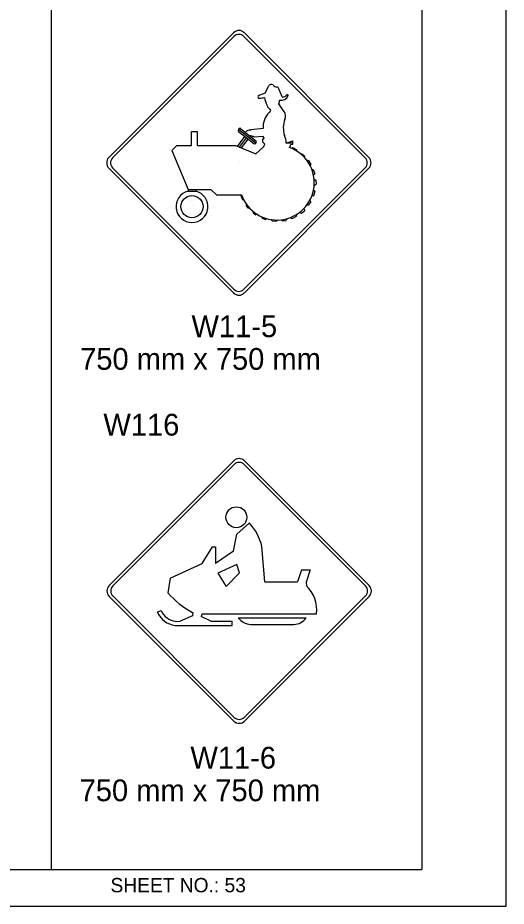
# Model space of a CAD drawing. Extents: x -12 to 6962, y -3756 to 679.
# Drawn here: x 2275 to 2342.4, y -235.4 to -112.9 of the extents above; entities that cross this region are included whole.
import ezdxf

# ---------------------------------------------------------------- set-up
doc = ezdxf.new("R2010")
doc.units = 0
for name, color, linetype in [('Level 1', 7, 'Continuous'), ('Level 2', 7, 'Continuous'), ('Level 3', 7, 'Continuous'), ('Level 62', 7, 'Continuous')]:
    doc.layers.add(name, color=color, linetype=linetype)

msp = doc.modelspace()

# ---------------------------------------------------------------- linework, layer by layer
at = {"layer": 'Level 1'}
for p, q in [((2279.62, -30.35), (2279.62, -230.35)), ((2330.8, -30.35), (2330.8, -230.35)), ((2287.6, -132.14), (2304.78, -114.96)), ((2306.28, -114.96), (2323.46, -132.14)), ((2288.09, -132.21), (2304.84, -115.45)), ((2306.21, -115.45), (2322.97, -132.21)), ((2309.16, -123.29), (2309.62, -122.34)), ((2311.49, -123.81), (2311.05, -122.67)), ((2311.8, -125.84), (2311.06, -124.74)), ((2299.01, -130.5), (2299.01, -128.58)), ((2299.01, -128.58), (2299.8, -128.58)), ((2299.8, -130.5), (2299.8, -128.58)), ((2305.46, -128.56), (2307.58, -130.24)), ((2305.47, -128.25), (2307.87, -130.15)), ((2305.77, -128.17), (2307.89, -129.85)), ((2308.86, -128.17), (2307.18, -128.32)), ((2307.18, -128.32), (2307.18, -128.39)), ((2305.32, -130.62), (2306.36, -129.28)), ((2305.6, -130.72), (2306.58, -129.46)), ((2305.87, -130.84), (2306.81, -129.63)), ((2307.64, -129.36), (2307.48, -129.2)), ((2308.9, -129.24), (2307.64, -129.36)), ((2308.83, -129.61), (2309.04, -129.48)), ((2308.83, -130.06), (2308.83, -129.61)), ((2309.04, -129.48), (2308.9, -129.24)), ((2312.05, -130.17), (2312.95, -129.84)), ((2312.95, -129.84), (2312.95, -130.34)), ((2296.96, -130.5), (2296.28, -131.19)), ((2296.96, -130.5), (2299.01, -130.5)), ((2299.8, -130.5), (2305.04, -130.5)), ((2305.04, -130.5), (2307.85, -131.64)), ((2307.85, -131.64), (2308.96, -130.66)), ((2309.13, -130.32), (2308.83, -130.06)), ((2308.96, -130.66), (2309.13, -130.32)), ((2312.2, -130.12), (2312.94, -130.12)), ((2312.95, -130.34), (2312.65, -130.42)), ((2312.77, -130.89), (2312.95, -130.79)), ((2312.95, -130.79), (2313.52, -131.08)), ((2313.54, -131.28), (2313.52, -131.08)), ((2296.28, -131.19), (2298.51, -136.55)), ((2314.01, -131.63), (2314.22, -131.63)), ((2314.22, -131.63), (2314.62, -131.98)), ((2314.58, -132.16), (2314.62, -131.98)), ((2305.55, -132.77), (2305.55, -132.77)), ((2314.85, -132.48), (2315.13, -132.57)), ((2315.13, -132.57), (2315.47, -133.13)), ((2315.4, -133.36), (2315.47, -133.13)), ((2304.78, -150.82), (2287.6, -133.64)), ((2304.85, -150.33), (2288.09, -133.58)), ((2322.97, -133.58), (2306.22, -150.33)), ((2323.46, -133.64), (2306.28, -150.82)), ((2315.57, -133.74), (2315.77, -133.8)), ((2315.77, -133.8), (2316, -134.41)), ((2315.83, -134.6), (2316, -134.41)), ((2315.91, -135.13), (2316.14, -135.29)), ((2315.92, -136.03), (2316.18, -135.83)), ((2316.14, -135.29), (2316.18, -135.83)), ((2298.51, -136.55), (2301.66, -136.55)), ((2298.51, -136.55), (2298.51, -136.8)), ((2298.51, -136.8), (2299.59, -136.8)), ((2299.59, -136.55), (2299.59, -136.8)), ((2301.66, -136.55), (2302.43, -137.32)), ((2315.83, -136.66), (2316.06, -136.78)), ((2315.89, -137.38), (2316.06, -136.78)), ((2302.43, -137.32), (2305.91, -137.32)), ((2305.91, -137.32), (2305.78, -137.49)), ((2305.78, -137.49), (2306.06, -138.01)), ((2306.25, -138.07), (2306.06, -138.01)), ((2315.2, -138.7), (2315.48, -138.3)), ((2315.33, -138.05), (2315.48, -138.3)), ((2315.61, -137.42), (2315.89, -137.38)), ((2306.54, -138.56), (2306.51, -138.8)), ((2306.51, -138.8), (2306.83, -139.15)), ((2307.06, -139.18), (2306.83, -139.15)), ((2307.46, -139.56), (2307.48, -139.78)), ((2314.19, -139.85), (2314.64, -139.47)), ((2314.51, -139.19), (2314.64, -139.47)), ((2314.94, -138.68), (2315.2, -138.7)), ((2307.48, -139.78), (2307.87, -140.07)), ((2308.09, -140.02), (2307.87, -140.07)), ((2308.65, -140.32), (2308.74, -140.52)), ((2308.74, -140.52), (2309.2, -140.7)), ((2309.37, -140.58), (2309.2, -140.7)), ((2309.95, -140.71), (2310.12, -140.89)), ((2310.88, -140.78), (2310.68, -140.93)), ((2311.41, -140.74), (2311.54, -140.91)), ((2311.54, -140.91), (2312.07, -140.83)), ((2312.16, -140.59), (2312.07, -140.83)), ((2312.67, -140.42), (2312.86, -140.57)), ((2312.86, -140.57), (2313.5, -140.26)), ((2313.43, -140.05), (2313.5, -140.26)), ((2313.87, -139.75), (2314.19, -139.85)), ((2310.12, -140.89), (2310.68, -140.93)), ((2287.64, -191.18), (2304.82, -173.99)), ((2288.13, -191.24), (2304.88, -174.49)), ((2306.25, -174.49), (2323, -191.24)), ((2306.32, -173.99), (2323.5, -191.18)), ((2305.24, -184.11), (2306.97, -182.53)), ((2304.78, -186.42), (2305.24, -184.11)), ((2300.48, -188.13), (2301.89, -185.85)), ((2301.89, -185.85), (2302.28, -185.85)), ((2302.28, -185.85), (2302.28, -188.14)), ((2309.12, -190.69), (2308.71, -185.81)), ((2304.78, -186.42), (2302.28, -188.14)), ((2296.05, -190.17), (2300.48, -188.13)), ((2305.25, -188.26), (2302.62, -189.45)), ((2305.63, -189.44), (2305.25, -188.26)), ((2302.62, -189.45), (2303.79, -191.3)), ((2303.79, -191.3), (2305.63, -189.44)), ((2314.16, -189.01), (2313.62, -190.69)), ((2314.16, -189.01), (2315.37, -189.01)), ((2315.37, -189.01), (2314.83, -190.71)), ((2296.05, -190.17), (2295.73, -192.17)), ((2309.12, -190.69), (2313.62, -190.69)), ((2314.83, -190.71), (2314.83, -190.71)), ((2314.83, -190.71), (2314.84, -191.16)), ((2305.58, -191.8), (2305.58, -191.8)), ((2304.82, -209.86), (2287.64, -192.67)), ((2304.88, -209.36), (2288.13, -192.61)), ((2323, -192.61), (2306.25, -209.36)), ((2323.5, -192.67), (2306.32, -209.86)), ((2294.27, -194.87), (2294.79, -194.64)), ((2299.12, -195.34), (2297.42, -196.1)), ((2299.15, -194.89), (2299.12, -195.34)), ((2300.44, -195.1), (2300.33, -195.43)), ((2301.67, -196.1), (2300.33, -195.43)), ((2300.44, -195.1), (2316.24, -195.1)), ((2305.45, -195.62), (2314.81, -195.62)), ((2296.73, -196.68), (2304.61, -196.68)), ((2296.8, -196.12), (2297.42, -196.1)), ((2301.67, -196.1), (2304.61, -196.1)), ((2304.61, -196.68), (2304.61, -196.1)), ((2307.14, -196.54), (2313.11, -196.54)), ((2179.04, -230.35), (2330.8, -230.35))]:
    msp.add_line(p, q, dxfattribs=at)
for centre, radius in [((2299.05, -138.93), 1.53), ((2305.18, -181.76), 1.44)]:
    msp.add_circle(centre, radius, dxfattribs=at)
for centre, radius, start, end in [((2305.53, -115.7), 1.06, 45, 135), ((2305.53, -116.14), 0.969, 45, 135), ((2310.01, -122.49), 0.42, 52.8758, 158.7594), ((2310.84, -121.72), 0.722, 217.228, 262.7381), ((2310.73, -122.78), 0.339, 17.4764, 86.1934), ((2308.32, -123.8), 0.17, 140.0734, 282.8144), ((2310.77, -128.57), 5.52, 106.9201, 117.8811), ((2311.35, -123.19), 1.08, 259.0915, 336.8952), ((2311.56, -123.04), 0.776, 264.8668, 321.526), ((2312.23, -123.61), 0.109, 1.4081, 125.4618), ((2308.25, -120.35), 3.62, 271.6893, 283.3893), ((2311.22, -123.8), 2.14, 181.8608, 212.9912), ((2310.14, -124.84), 0.721, 190.052, 251.6858), ((2309.98, -124.3), 1.17, 337.7005, 2.5722), ((2311.83, -128.02), 2.97, 135.7669, 182.7567), ((2309.61, -125.64), 0.323, 285.4361, 21.4455), ((2310.98, -126.41), 0.994, 331.6787, 34.2982), ((2315.15, -128.05), 3.49, 160.3322, 198.0298), ((2305.67, -128.41), 0.256, 65.5805, 217.6676), ((2307.04, -129.14), 0.761, 79.4167, 142.3349), ((2307.17, -129.24), 0.0938, 57.4362, 163.671), ((2307.38, -128.96), 0.252, 231.9989, 293.1543), ((2307.68, -130), 0.259, 247.6658, 35.5822), ((2310.1, -130.05), 1.95, 356.6271, 28.0547), ((2310.78, -135.63), 5.15, 199.0393, 70.7748), ((2312.32, -130.47), 0.341, 299.14, 7.7446), ((2288.34, -132.89), 1.06, 135, 225), ((2288.78, -132.89), 0.969, 135, 225), ((2322.28, -132.89), 0.969, 315, 45), ((2322.72, -132.89), 1.06, 315, 45), ((2299.05, -138.93), 2.2, 104.2732, 75.7269), ((2299.05, -138.93), 0.861, 104.24961944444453, 104.24962222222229), ((2299.05, -138.93), 0.191, 75.71255000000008, 75.71255277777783), ((2305.53, -149.64), 0.969, 225, 315), ((2305.53, -150.08), 1.06, 225, 315), ((2305.57, -174.74), 1.06, 45, 135), ((2305.57, -175.17), 0.969, 45, 135), ((2301.31, -187.65), 7.63, 13.962, 42.1299), ((2288.38, -191.92), 1.06, 135, 225), ((2288.82, -191.92), 0.969, 135, 225), ((2304.15, -185.12), 10.98, 219.9752, 242.9053), ((2311.59, -194.54), 4.68, 353.1049, 46.1529), ((2322.32, -191.92), 0.969, 315, 45), ((2322.76, -191.92), 1.06, 315, 45), ((2297.11, -193.59), 2.54, 204.3781, 263.0543), ((2297.11, -193.59), 3.11, 204.3781, 263.0543), ((2307.27, -194.3), 2.25, 215.9203, 266.8132), ((2313.1, -194.5), 2.04, 270.4082, 326.8583), ((2305.57, -208.67), 0.969, 225, 315), ((2305.57, -209.11), 1.06, 225, 315)]:
    msp.add_arc(centre, radius, start, end, dxfattribs=at)
at = {"layer": 'Level 62'}
msp.add_lwpolyline([(2167.17, -235.4), (2342.43, -235.4), (2342.43, -22.31), (2167.17, -22.31)], close=True, dxfattribs=at)

# ---------------------------------------------------------------- texts
at = {"layer": 'Level 2'}
msp.add_text('W116', height=3, dxfattribs=at).set_placement((2286.83, -170.5))
at = {"layer": 'Level 3'}
for s, height, p in [('W11-5', 3, (2298.99, -156.93)), ('750 mm x 750 mm', 3, (2283.62, -161.43)), ('W11-6', 3, (2298.84, -216.42)), ('750 mm x 750 mm', 3, (2283.55, -220.92)), ('SHEET NO.: 53', 1.9795, (2287.81, -233.48))]:
    msp.add_text(s, height=height, dxfattribs=at).set_placement(p)

doc.saveas('drawing.dxf')
